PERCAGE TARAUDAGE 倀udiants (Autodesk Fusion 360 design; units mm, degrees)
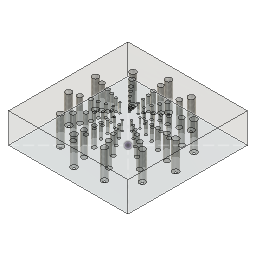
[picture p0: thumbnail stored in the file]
sketch "Esquisse" plane through (0, 0, 0) normal (0, 0, 1) x axis (1, 0, 0)
  line L1 (-100, -100) -> (100, -100)
  line L2 (-100, 100) -> (-100, -100)
  line L3 (100, 100) -> (-100, 100)
  line L4 (100, -100) -> (100, 100)
  line L5 (-100, 100) -> (100, -100)
  line L6 (100, 100) -> (-100, -100)
  point P6 (0, 0)
  point P1 (0, 0)
  point P4 (-100, 100)
  point P5 (100, 100)
  point P3 (-100, -100)
  horizontal L1
  perpendicular L1 L2
  parallel L1 L3
  parallel L2 L4
  coincident L5 P6
  coincident L6 P6
  coincident P1 P6
  dimension "d10" distance P4 P5 = 200
  dimension "d11" distance P3 P4 = 200
extrude "Extrusion" new body sketch "Esquisse" profile of L1 L2 L3 L4 along normal blind 50
hole "Perçage1" HoleDepth 16 HoleDiameter 3.332 RefDim1 100 RefDim2 80
hole "Perçage2" HoleDepth 20 HoleDiameter 4.234 RefDim1 100 RefDim2 70
hole "Perçage3" HoleDepth 24 HoleDiameter 5.035 RefDim1 100 RefDim2 60
hole "Perçage4" HoleDepth 32 HoleDiameter 6.7795 RefDim1 100 RefDim2 50
hole "Perçage5" HoleDepth 40 HoleDiameter 8.526 RefDim1 100 RefDim2 35
hole "Perçage6" HoleDepth 48 HoleDiameter 10.2735 RefDim1 100 RefDim2 20
circular_pattern "Réseau C" countU 11
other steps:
thread "Filetage1" ThreadOffset 0 ThreadDepth 10
thread "Filetage2" ThreadOffset 0 ThreadDepth 12.5
thread "Filetage3" ThreadOffset 0 ThreadDepth 15
thread "Filetage4" ThreadOffset 0 ThreadDepth 20
thread "Filetage5" ThreadOffset 0 ThreadDepth 25
thread "Filetage6" ThreadOffset 0 ThreadDepth 30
